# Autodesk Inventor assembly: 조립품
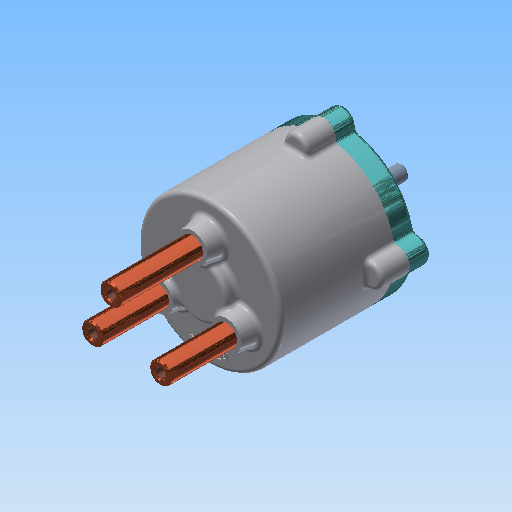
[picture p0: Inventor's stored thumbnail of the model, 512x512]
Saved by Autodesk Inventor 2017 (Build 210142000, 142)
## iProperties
Part Number: 조립품
Material: 일반
Document SubType Name: Assembly
Designer: MRC
Author: MRC
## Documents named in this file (14)
- C:\Users\MRC\Desktop\610708V1013\610708V1013\조립품.iam
- C:\Users\MRC\Desktop\610708V1013\610708V1013\본체.ipt
- C:\Users\MRC\Desktop\610708V1013\610708V1013\멈춤링 10 x 1.ipt
- C:\Users\MRC\Desktop\610708V1013\610708V1013\멈춤링 22 x 1.2.ipt
- C:\Users\MRC\Desktop\610708V1013\610708V1013\메인 축.ipt
- C:\Users\MRC\Desktop\610708V1013\610708V1013\베어링 NA 4900.ipt
- C:\Users\MRC\Desktop\610708V1013\610708V1013\볼트 M5.ipt
- C:\Users\MRC\Desktop\610708V1013\610708V1013\슬라이드 축.ipt
- C:\Users\MRC\Desktop\610708V1013\610708V1013\오일실.ipt
- C:\Users\MRC\Desktop\610708V1013\610708V1013\커버.ipt
- C:\Users\MRC\Desktop\610708V1013\610708V1013\판캠.ipt
- C:\Users\MRC\Desktop\610708V1013\610708V1013\스프링1.ipt
- C:\Users\MRC\Desktop\610708V1013\610708V1013\스프링2.ipt
- C:\Users\MRC\Desktop\610708V1013\610708V1013\스프링3.ipt
